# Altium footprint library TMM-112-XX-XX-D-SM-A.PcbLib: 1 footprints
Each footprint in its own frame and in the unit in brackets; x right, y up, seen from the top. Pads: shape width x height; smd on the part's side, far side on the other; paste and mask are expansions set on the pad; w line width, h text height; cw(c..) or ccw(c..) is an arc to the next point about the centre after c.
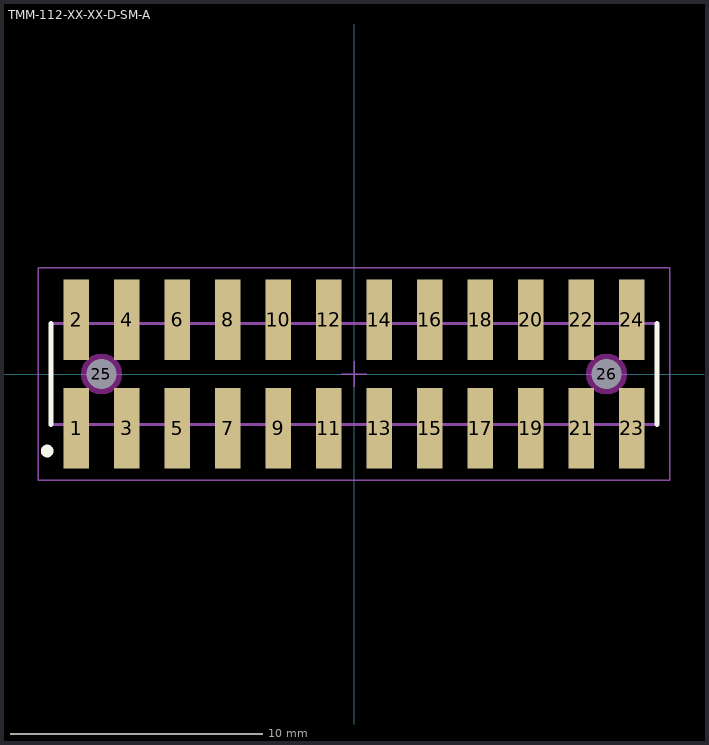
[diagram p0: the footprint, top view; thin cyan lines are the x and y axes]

## TMM-112-XX-XX-D-SM-A [mm] "2.00mm pitch, 24 pin, terminal strip; double row, w/alignment pins, SMT"
height 2.77
pads (26):
  rect 1x3.2 smd mask+0: 1(-11,-2.15) 2(-11,2.15) 3(-9,-2.15) 4(-9,2.15) 5(-7,-2.15) 6(-7,2.15) 7(-5,-2.15) 8(-5,2.15) 9(-3,-2.15) 10(-3,2.15) 11(-1,-2.15) 12(-1,2.15) 13(1,-2.15) 14(1,2.15) 15(3,-2.15) 16(3,2.15) 17(5,-2.15) 18(5,2.15) 19(7,-2.15) 20(7,2.15) 21(9,-2.15) 22(9,2.15) 23(11,-2.15) 24(11,2.15)
  round 1 hole 1.2 unplated mask+0: 25(-10,0) 26(10,0)
Top Overlay:
  circle w0.25: c-12.15,-3.05 r0.125
  lines w0.2: -12,-2 -12,2 ; 12,-2 12,2
Keep-Out Layer:
  pour cut-out: -9.193,0 -9.221,0.209 -9.301,0.403 -9.429,0.571 -9.597,0.699 -9.791,0.779 -10,0.807 -10.209,0.779 -10.403,0.699 -10.571,0.571 -10.699,0.403 -10.779,0.209 -10.807,0 -10.779,-0.209 -10.699,-0.403 -10.571,-0.571 -10.403,-0.699 -10.209,-0.779 -10,-0.807 -9.791,-0.779 -9.597,-0.699 -9.429,-0.571 -9.301,-0.403 -9.221,-0.209
  pour cut-out: 10.807,0 10.779,0.209 10.699,0.403 10.571,0.571 10.403,0.699 10.209,0.779 10,0.807 9.791,0.779 9.597,0.699 9.429,0.571 9.301,0.403 9.221,0.209 9.193,0 9.221,-0.209 9.301,-0.403 9.429,-0.571 9.597,-0.699 9.791,-0.779 10,-0.807 10.209,-0.779 10.403,-0.699 10.571,-0.571 10.699,-0.403 10.779,-0.209
Mechanical 12:
  lines w0.001: -12,-2 12,-2 12,2 -12,2 -12,-2
Mechanical 13:
  lines w0.1: -12,-2 12,-2 12,2 -12,2 -12,-2
  text ".Designator" at 0,0 h1.52
Mechanical 15:
  lines w0.05: -0.5,0 0.5,0 ; 0,-0.5 0,0.5 ; -12.5,-4.2 12.5,-4.2 12.5,4.2 -12.5,4.2 -12.5,-4.2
